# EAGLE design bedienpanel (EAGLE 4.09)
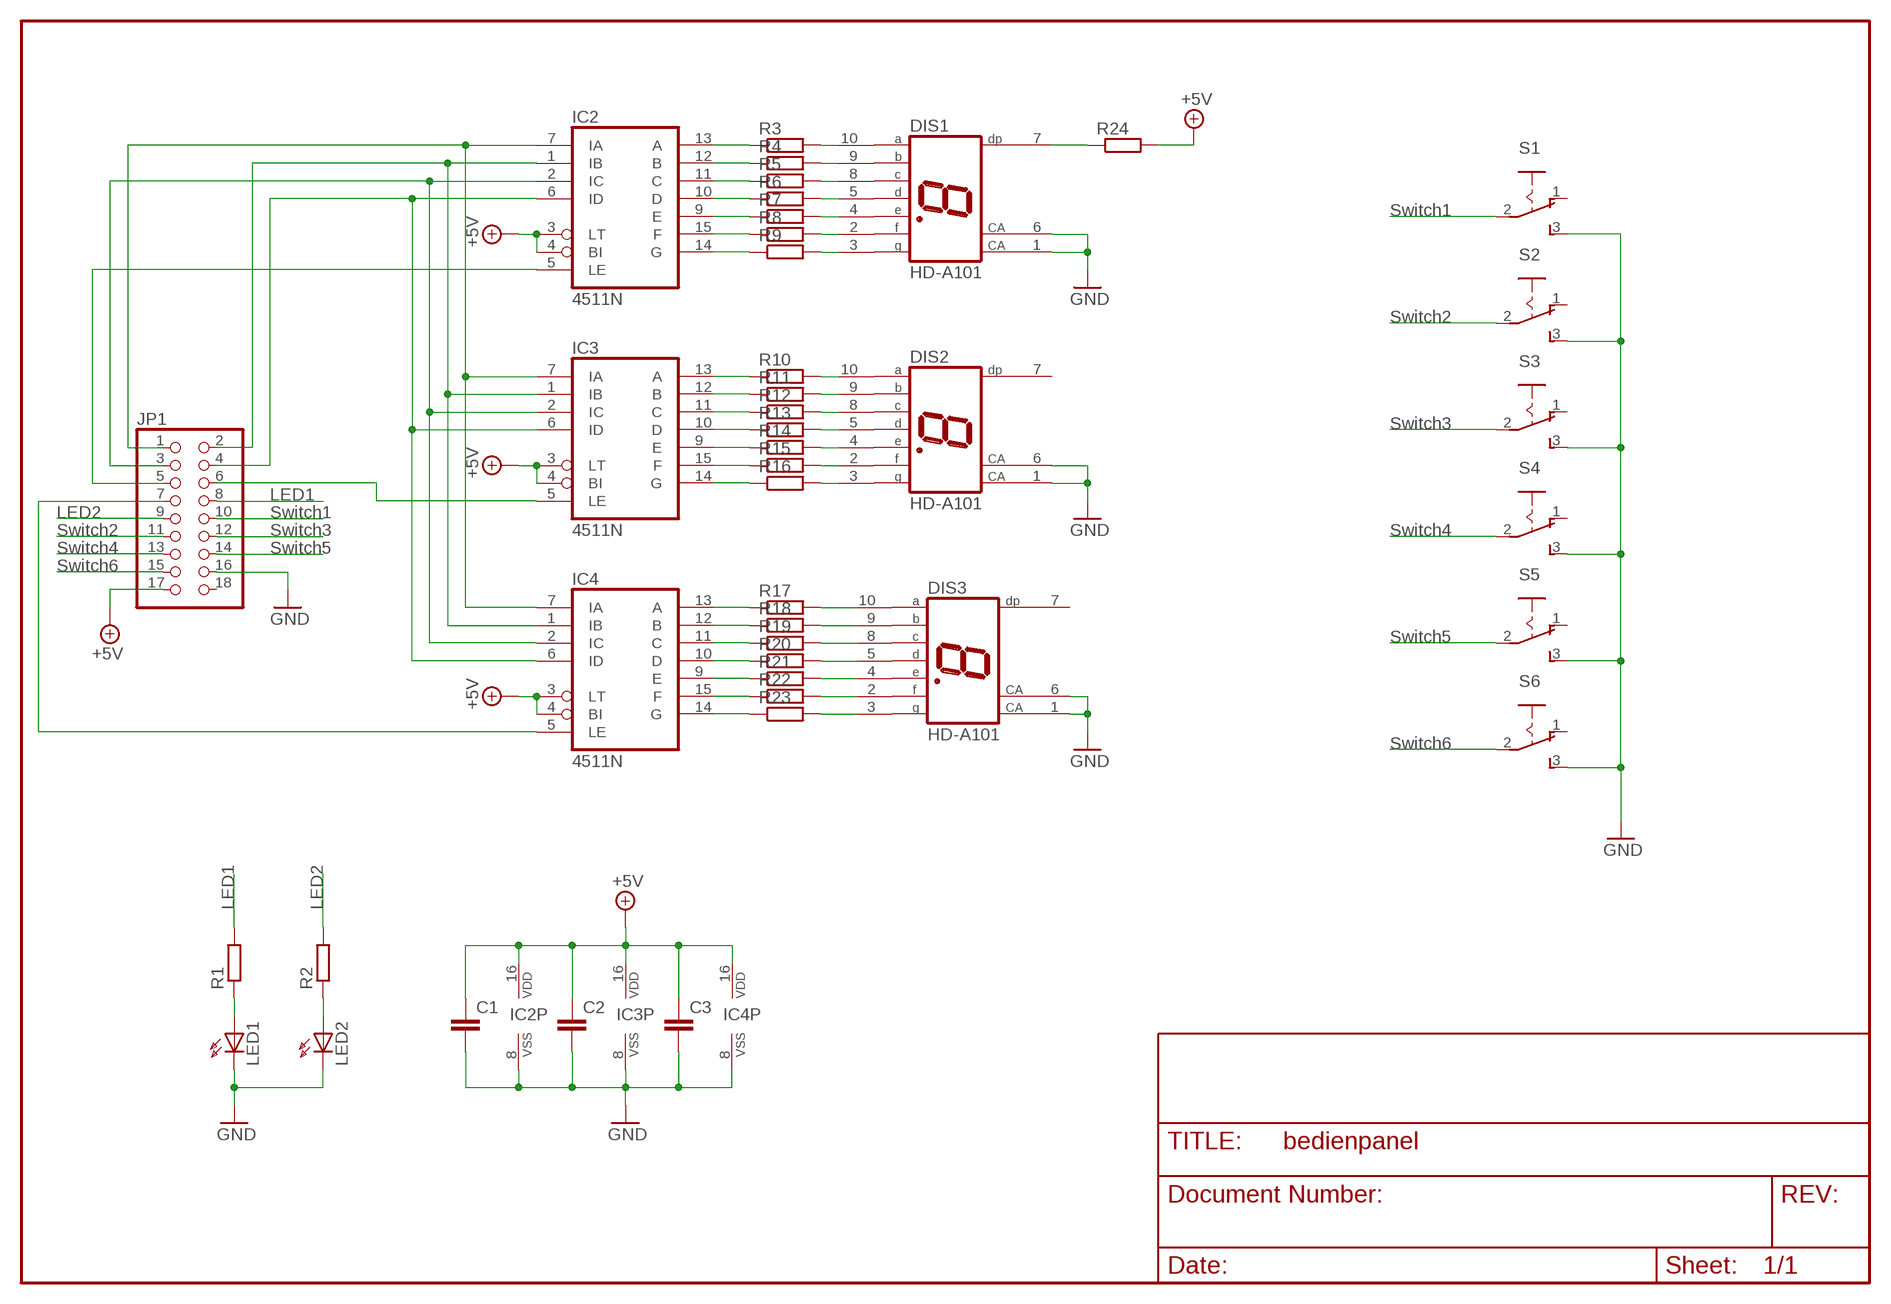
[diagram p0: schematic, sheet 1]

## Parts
C1  C-EUC1206  [C1206]
C2  C-EUC1206  [C1206]
C3  C-EUC1206  [C1206]
DIS1  HD-A101  [HDSP-A]
DIS2  HD-A101  [HDSP-A]
DIS3  HD-A101  [HDSP-A]
IC2  4511N  [DIL16]
IC3  4511N  [DIL16]
IC4  4511N  [DIL16]
JP1  PINHD-2X9  [2X09]
LED1  LED3MM  [LED3MM]
LED2  LED3MM  [LED3MM]
R1  R-EU_R1206  [R1206]
R2  R-EU_R1206  [R1206]
R3  R-EU_M0805  [M0805]
R4  R-EU_M0805  [M0805]
R5  R-EU_M0805  [M0805]
R6  R-EU_M0805  [M0805]
R7  R-EU_M0805  [M0805]
R8  R-EU_M0805  [M0805]
R9  R-EU_M0805  [M0805]
R10  R-EU_M0805  [M0805]
R11  R-EU_M0805  [M0805]
R12  R-EU_M0805  [M0805]
R13  R-EU_M0805  [M0805]
R14  R-EU_M0805  [M0805]
R15  R-EU_M0805  [M0805]
R16  R-EU_M0805  [M0805]
R17  R-EU_M0805  [M0805]
R18  R-EU_M0805  [M0805]
R19  R-EU_M0805  [M0805]
R20  R-EU_M0805  [M0805]
R21  R-EU_M0805  [M0805]
R22  R-EU_M0805  [M0805]
R23  R-EU_M0805  [M0805]
R24  R-EU_M0805  [M0805]
S1  255SB  [255SB]
S2  255SB  [255SB]
S3  255SB  [255SB]
S4  255SB  [255SB]
S5  255SB  [255SB]
S6  255SB  [255SB]

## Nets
+5V: C1.1 C2.1 C3.1 IC2.3(LT) IC2.4(BI) IC2.16(VDD) IC3.3(LT) IC3.4(BI) IC3.16(VDD) IC4.3(LT) IC4.4(BI) IC4.16(VDD) JP1.17 R24.2
GND: C1.2 C2.2 C3.2 DIS1.1(CA) DIS1.6(CA) DIS2.1(CA) DIS2.6(CA) DIS3.1(CA) DIS3.6(CA) IC2.8(VSS) IC3.8(VSS) IC4.8(VSS) JP1.16 LED1.K(C) LED2.K(C) S1.3(S) S2.3(S) S3.3(S) S4.3(S) S5.3(S) S6.3(S)
LED1: JP1.8 R1.2
LED2: JP1.9 R2.2
N$1: IC2.6(ID) IC3.6(ID) IC4.6(ID) JP1.4
N$2: IC2.7(IA) IC3.7(IA) IC4.7(IA) JP1.1
N$3: IC2.5(LE) JP1.5
N$4: IC2.2(IC) IC3.2(IC) IC4.2(IC) JP1.3
N$5: IC2.1(IB) IC3.1(IB) IC4.1(IB) JP1.2
N$6: IC3.5(LE) JP1.6
N$7: IC4.5(LE) JP1.7
N$8: IC2.13(A) R3.1
N$9: IC2.12(B) R4.1
N$10: IC2.11(C) R5.1
N$11: IC2.10(D) R6.1
N$12: IC2.9(E) R7.1
N$13: IC2.15(F) R8.1
N$14: IC2.14(G) R9.1
N$15: IC3.13(A) R10.1
N$16: IC3.12(B) R11.1
N$17: IC3.11(C) R12.1
N$18: IC3.10(D) R13.1
N$19: IC3.9(E) R14.1
N$20: IC3.15(F) R15.1
N$21: IC3.14(G) R16.1
N$22: IC4.13(A) R17.1
N$23: IC4.12(B) R18.1
N$24: IC4.11(C) R19.1
N$25: IC4.10(D) R20.1
N$26: IC4.9(E) R21.1
N$27: IC4.15(F) R22.1
N$28: IC4.14(G) R23.1
N$29: LED1.A R1.1
N$30: LED2.A R2.1
N$31: DIS1.10(A) R3.2
N$32: DIS1.9(B) R4.2
N$33: DIS1.8(C) R5.2
N$34: DIS1.5(D) R6.2
N$35: DIS1.4(E) R7.2
N$36: DIS1.2(F) R8.2
N$37: DIS1.3(G) R9.2
N$38: DIS2.10(A) R10.2
N$39: DIS2.9(B) R11.2
N$40: DIS2.8(C) R12.2
N$41: DIS2.5(D) R13.2
N$42: DIS2.4(E) R14.2
N$43: DIS2.2(F) R15.2
N$44: DIS2.3(G) R16.2
N$45: DIS3.10(A) R17.2
N$46: DIS3.9(B) R18.2
N$47: DIS3.8(C) R19.2
N$48: DIS3.5(D) R20.2
N$49: DIS3.4(E) R21.2
N$50: DIS3.2(F) R22.2
N$51: DIS3.3(G) R23.2
N$52: DIS1.7(DP) R24.1
SWITCH1: JP1.10 S1.2(P)
SWITCH2: JP1.11 S2.2(P)
SWITCH3: JP1.12 S3.2(P)
SWITCH4: JP1.13 S4.2(P)
SWITCH5: JP1.14 S5.2(P)
SWITCH6: JP1.15 S6.2(P)
Unconnected: DIS2.7(DP) DIS3.7(DP) JP1.18 S1.1(O) S2.1(O) S3.1(O) S4.1(O) S5.1(O) S6.1(O)

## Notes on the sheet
- Switch1
- Switch2
- Switch3
- LED1
- LED2 | Switch1
- Switch2 | Switch3 | Switch4
- Switch4 | Switch5
- Switch6
- Switch5
- Switch6
- LED1 | LED2

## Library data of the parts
C1-C3 = rcl:C-EU: CAPACITOR, European symbol
DIS1-DIS3 = display-hp:HD-A101: LED DISPLAY 1-character 7 segment, decimal point right
IC2-IC4 = 45xx:4511: BCD to 7-segment LATCH/DECODER/DRIVER
JP1 = pinhead:PINHD-2X9: PIN HEADER
LED1 LED2 = led:LED: LED
R1-R24 = rcl:R-EU_: RESISTOR, European symbol
S1-S6 = switch:255SB: SLIDING SWITCH distributor Buerklin, 11G810

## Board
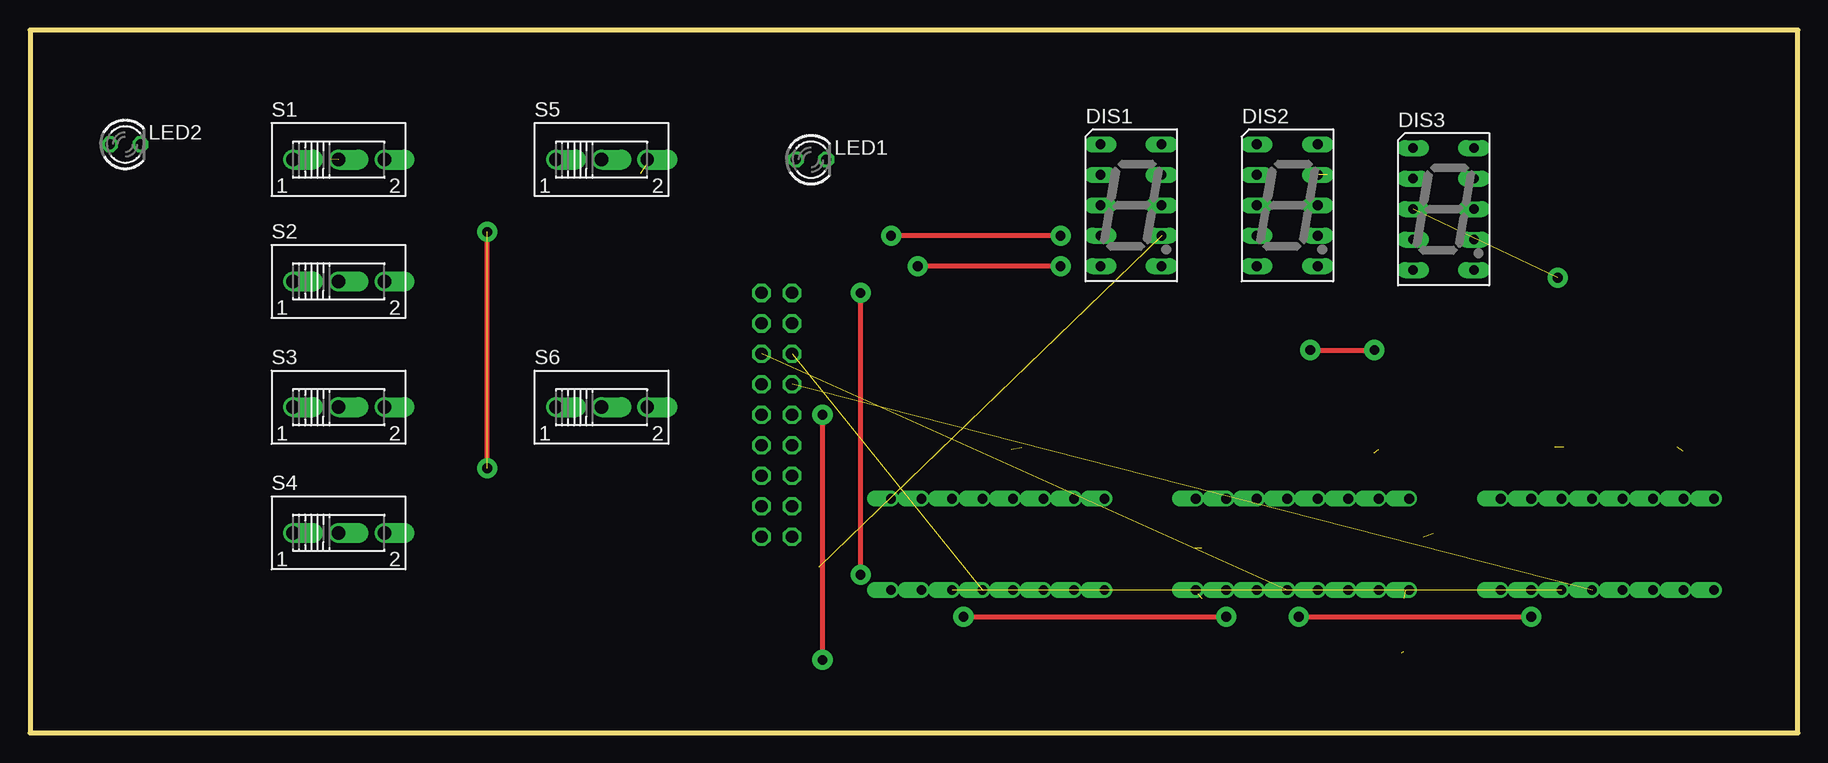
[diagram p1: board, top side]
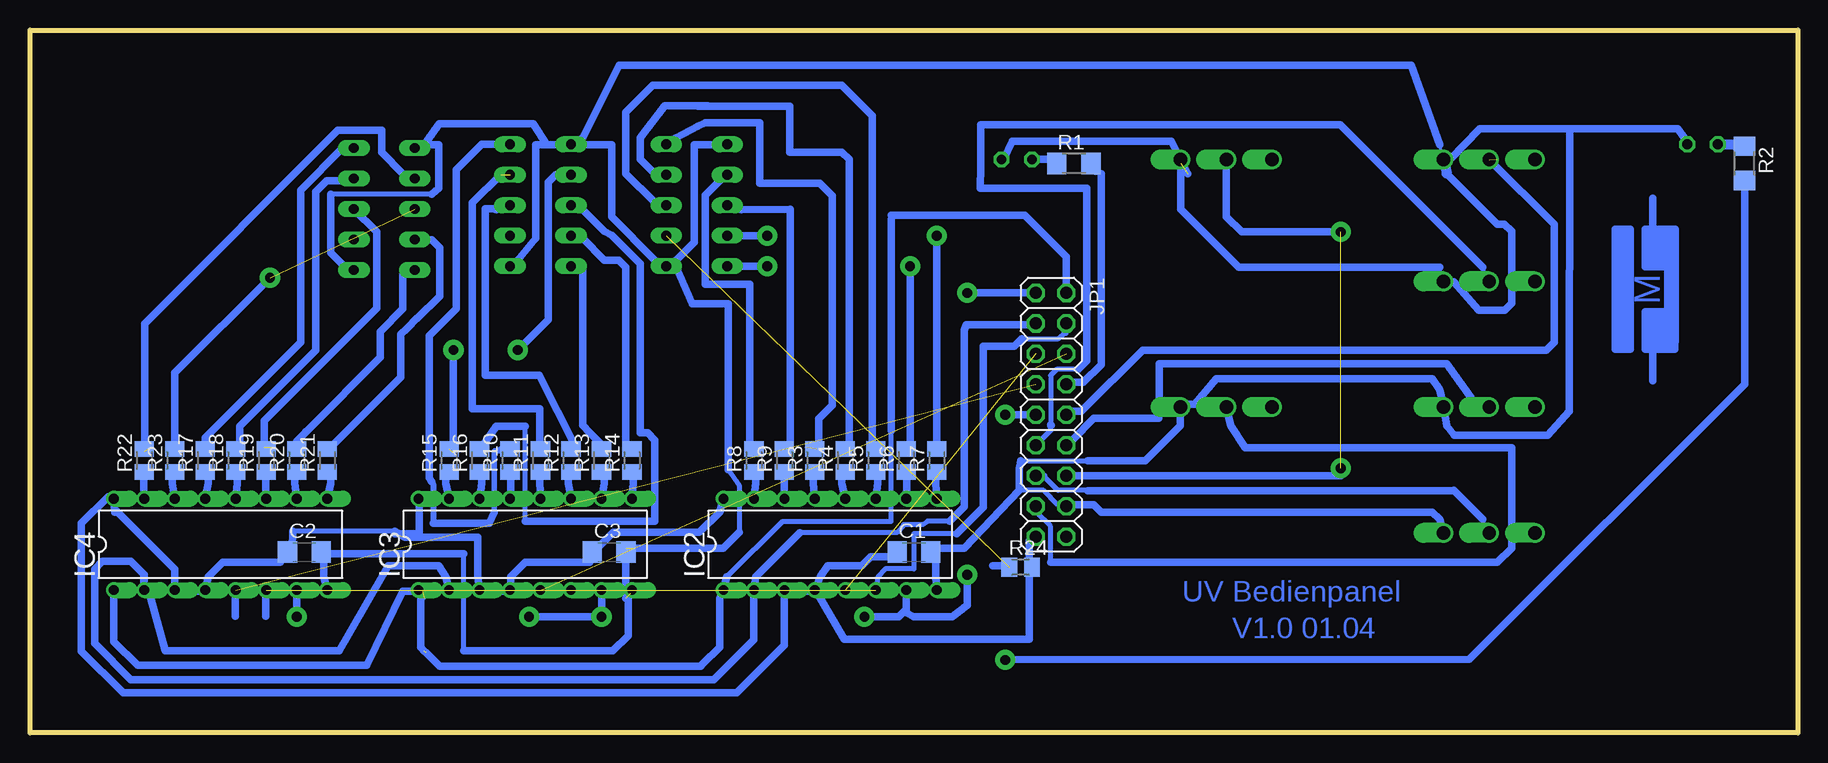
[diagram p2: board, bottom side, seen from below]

Size 147.32 x 58.58 mm. Coordinates in mm from the lower left corner, seen from the top.
Outline: 0,0 147.32,0 147.32,58.58 0,58.58 0,0
Copper layers used: Top, Bottom

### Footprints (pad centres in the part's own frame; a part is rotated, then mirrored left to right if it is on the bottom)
C1206 = smd 1.6 x 1.8: 1 -1.4,0; 2 1.4,0
HDSP-A = drill 0.813 long: 1 -2.54,5.08; 2 -2.54,2.54; 3 -2.54,0; 4 -2.54,-2.54; 5 -2.54,-5.08; 6 2.54,-5.08; 7 2.54,-2.54; 8 2.54,0; 9 2.54,2.54; 10 2.54,5.08
DIL16 = drill 0.813 offset: 1 -8.89,-3.81; 2 -6.35,-3.81; 3 -3.81,-3.81; 4 -1.27,-3.81; 5 1.27,-3.81; 6 3.81,-3.81; 7 6.35,-3.81; 8 8.89,-3.81; 9 8.89,3.81; 10 6.35,3.81; 11 3.81,3.81; 12 1.27,3.81; 13 -1.27,3.81; 14 -3.81,3.81; 15 -6.35,3.81; 16 -8.89,3.81
2X09 = drill 1.016 octagon: 1 -10.16,-1.27; 2 -10.16,1.27; 3 -7.62,-1.27; 4 -7.62,1.27; 5 -5.08,-1.27; 6 -5.08,1.27; 7 -2.54,-1.27; 8 -2.54,1.27; 9 0,-1.27; 10 0,1.27; 11 2.54,-1.27; 12 2.54,1.27; 13 5.08,-1.27; 14 5.08,1.27; 15 7.62,-1.27; 16 7.62,1.27; 17 10.16,-1.27; 18 10.16,1.27
LED3MM = drill 0.813 octagon: A -1.27,0; K 1.27,0
R1206 = smd 1.6 x 1.803: 1 -1.422,0; 2 1.422,0
M0805 = smd 1.3 x 1.6: 1 -0.95,0; 2 0.95,0
255SB = drill 1.118 offset: 1 -3.81,0; 2 0,0; 3 3.81,0

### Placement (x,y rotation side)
C1  73.66,15.08 0 bottom
C2  124.46,15.08 0 bottom
C3  99.06,15.08 0 bottom
DIS1  91.76,43.97 0 top
DIS2  104.77,43.97 0 top
DIS3  117.79,43.66 0 top
IC2  80.64,15.72 0 bottom
IC3  106.05,15.72 0 bottom
IC4  131.45,15.72 0 bottom
JP1  62.23,26.51 270 bottom
LED1  65.09,47.78 0 top
LED2  7.94,49.05 0 top
R1  60.33,47.47 0 bottom
R2  4.44,47.47 270 bottom
R3  81.91,22.7 90 bottom
R4  79.38,22.7 90 bottom
R5  76.83,22.7 90 bottom
R6  74.3,22.7 90 bottom
R7  71.75,22.7 90 bottom
R8  86.99,22.7 90 bottom
R9  84.45,22.7 90 bottom
R10  107.31,22.7 90 bottom
R11  104.77,22.7 90 bottom
R12  102.23,22.7 90 bottom
R13  99.69,22.7 90 bottom
R14  97.16,22.7 90 bottom
R15  112.39,22.7 90 bottom
R16  109.85,22.7 90 bottom
R17  132.72,22.7 90 bottom
R18  130.18,22.7 90 bottom
R19  127.63,22.7 90 bottom
R20  125.09,22.7 90 bottom
R21  122.55,22.7 90 bottom
R22  137.8,22.7 90 bottom
R23  135.26,22.7 90 bottom
R24  64.77,13.81 0 bottom
S1  25.72,47.78 0 top
S2  25.72,37.62 0 top
S3  25.72,27.15 0 top
S4  25.72,16.67 0 top
S5  47.62,47.78 0 top
S6  47.62,27.15 0 top
U$1  [LOGO]  12.73,36.96 270 top

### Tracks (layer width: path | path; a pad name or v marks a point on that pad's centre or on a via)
+5V  (1 unrouted)
  Bottom 0.254: 109.66,11.81 IC3.3 | 100.06,15.41 C3.1 100.66,14.21 | 64.06,14.21 R24.2 64.06,13.61 | IC2.4 82.06,11.81 | 75.46,14.68 C1.1 | IC4.4 133.06,11.81 | 134.86,11.81 IC4.3 | 125.48,15.41 C2.1 126.46,14.21
  Bottom 0.406: 116.92,16.83 125.43,16.83
  Bottom 0.61: 109.66,11.81 107.86,11.81 IC3.4 107.26,13.01 106.06,14.21 100.66,14.21 | 100.06,15.41 98.74,16.73 91.54,16.73 89.86,18.41 IC2.16 | 64.06,14.21 64.06,16.01 JP1.17 | 82.06,11.81 83.86,11.81 IC2.3 84.46,7.43 84.46,7.3 88.42,3.33 139.54,3.33 143.03,6.83 143.03,17.46 140.86,19.64 | 75.46,14.68 77.26,14.68 78.02,13.92 80.86,13.92 81.46,13.01 IC2.4 81.46,11.21 79.47,7.82 64.06,7.82 64.06,13.61 | 133.06,11.81 134.86,11.81 | 116.92,16.83 116.1,16.32 110.01,16.32 110.01,13.01 IC3.3 | 125.43,16.83 125.48,15.41 | IC3.16 114.9,18.41 114.9,16.6 116.94,16.6 | 126.46,14.21 131.26,14.21 132.46,13.01 IC4.4 | IC4.3 135.25,13.65 140.18,18.57 140.26,18.49 140.26,18.41 IC4.16 140.86,19.61 140.86,19.64 | 140.81,19.69 140.86,19.64
GND  (3 unrouted)
  Bottom 0.254: 122.86,14.94 C2.2 | DIS2.1 101.26,49.01 | 97.06,15.41 C3.2 | DIS1.6 93.46,38.81 | 71.86,14.21 C1.2 71.86,15.41 | 61.66,19.01 JP1.16 60.46,19.01 | 28.95,47.81 29.26,47.81 | 29.86,38.81 S2.3 29.26,37.61 28.66,37.61 | S1.3 29.86,49.01
  Bottom 0.406: 111.18,6.83 111.18,14.94 | 113.86,44.89 122.26,44.89 | 89.14,21.92 88.22,20.65 88.22,16.72 | 61.66,19.01 62.86,20.21 64.87,20.21 | 64.75,22.7 54.38,22.7
  Bottom 0.61: C3.2 97.66,12.41 IC3.8 97.66,11.21 | IC4.8 122.86,13.01 122.86,14.94 111.18,14.94 | DIS1.1 90.46,49.01 91.98,49.01 91.98,40.89 93.46,39.41 DIS1.6 95.26,39.41 98.86,43.01 98.86,49.01 101.26,49.01 | 104.26,49.01 103.06,49.01 DIS2.1 101.26,49.61 98.22,55.66 32.22,55.66 29.86,49.01 | 104.26,49.01 105.18,49.01 105.18,41.21 106.66,39.41 DIS2.6 | 114.46,49.01 113.2,50.75 105.4,50.75 104.26,49.01 | 122.26,44.89 122.26,40.01 121.06,38.81 DIS3.6 | 113.86,44.89 113.26,45.41 113.26,49.01 114.46,49.01 | 114.46,49.01 DIS3.1 | 89.14,21.92 89.14,35.77 92.14,35.77 93.46,38.81 | 71.86,14.21 71.86,13.01 IC2.8 | 71.86,15.41 69.46,15.41 64.87,20.21 64.87,22.01 64.75,22.7 | 60.46,19.01 58.66,19.01 58.06,18.41 30.46,18.41 29.86,17.81 S4.3 | 54.38,22.7 51.46,25.61 S6.3 50.86,27.41 50.26,27.41 48.46,29.52 30.46,29.52 29.86,28.61 S3.3 29.26,25.61 28.63,24.8 20.83,24.8 19.06,26.81 19.03,50.37 | 19.03,50.37 26.51,50.37 28.95,47.81 | 19.03,50.37 10.03,50.37 9.46,49.61 LED2.K | LED1.K 66.18,47.81 65.45,49.32 52.22,49.32 S5.3 50.86,46.61 | 29.26,46.61 25.06,42.41 24.46,42.41 23.86,41.81 23.86,35.81 23.82,35.81 24.42,35.21 26.58,35.21 28.66,37.61 | 29.86,38.81 46.58,38.81 51.43,43.66 51.43,47.47 | 88.22,16.72 89.53,15.4 97.63,15.4 | 111.18,6.83 98.74,6.83 97.47,8.1 97.47,11.43 97.31,11.59
  Bottom 0.813: 29.26,47.81 S1.3 29.26,46.61
LED1
  Bottom 0.254: 58.06,46.61 58.66,46.61 R1.2
  Bottom 0.61: JP1.8 60.46,29.21 59.53,29.21 58.06,30.68 58.06,46.61
LED2  (via drill 0.81 pad 1.68)
  Top 0.406: v66.04,26.51 v66.04,6.09
  Bottom 0.406: v66.04,26.51 JP1.9
  Bottom 0.61: JP1.9 v66.04,26.51 | v66.04,6.09 27.37,6.12 4.44,29.05 R2.2
N$1  (2 unrouted)
  Bottom 0.406: 70.09,16.61 73.66,16.61 73.66,13.67 76.06,13.67 76.66,13.01 IC2.6 | 64.66,32.87 61.63,32.87 61.06,33.41
  Bottom 0.61: 70.09,16.61 67.88,18.8 67.88,32.21 65.29,32.21 64.66,32.87 | 61.06,33.41 JP1.4
N$2  (via drill 0.81 pad 1.68)
  Top 0.406: v69.21,13.18 v69.21,36.67 | v77.79,9.68 v99.69,9.68 | v105.73,9.68 v125.09,9.68
  Bottom 0.406: IC2.7 74.29,10 | v99.69,9.68 IC3.7 | 125.09,11.59 125.41,11.91
  Bottom 0.61: 74.29,10 73.66,9.68 70.48,9.68 69.21,10.64 v69.21,13.18 | v69.21,36.67 JP1.1 | IC2.7 74.29,10.32 74.93,9.68 v77.79,9.68 | IC3.7 v99.69,9.68 v105.73,9.68 | 125.41,11.91 IC4.7 | v125.09,9.68 125.09,11.59
N$3  (1 unrouted)
N$4
  Bottom 0.254: 64.06,34.01 JP1.3
  Bottom 0.406: 70.66,17.65 72.52,17.65 72.93,17.36 74.52,17.36 75.06,16.7 83.15,16.7 | 86.85,13.01 86.86,13.01
  Bottom 0.61: IC3.2 112.66,13.01 113.26,13.92 117.46,13.92 121.54,6.83 136.06,6.83 137.26,11.21 IC4.2 137.86,13.01 137.79,12.94 | 70.66,17.65 69.46,18.85 69.46,33.55 69.3,34 65.26,34.01 64.06,34.01 | 86.86,13.01 IC2.2 | 83.15,16.7 86.85,13.01 | 86.99,12.07 IC2.2 | IC2.2 86.99,7.78 90.33,4.45 138.91,4.45 141.92,7.46 141.92,13.65 141.29,14.29 138.91,14.29 137.79,13.18 137.79,12.94 | 137.79,12.7 137.79,12.94
N$5  (2 unrouted)
  Bottom 0.254: 114.46,11.21 IC3.1 115.06,11.81
  Bottom 0.406: 75.55,43.16 75.55,17.62 84.62,17.62 89.26,13.01
  Bottom 0.61: 115.06,11.81 116.26,11.81 119.26,5.63 138.35,5.63 140.33,7.62 IC4.1 | 75.55,43.16 64.41,43.14 60.96,39.69 JP1.2 | 89.26,13.01 IC2.1 89.86,11.21 89.86,7.14 91.28,5.72 | 91.28,5.72 | 91.28,5.72 91.44,5.56 113.19,5.56 114.3,6.67 | 114.3,6.67 | 114.46,6.83 | 114.78,11.75 114.62,11.91 | 114.78,11.91 114.78,11.75 | 114.46,6.83 114.78,7.14 114.78,11.75
N$6  (1 unrouted)
N$7  (1 unrouted)
N$8
  Bottom 0.254: R3.1 82.06,21.41
  Bottom 0.61: 82.06,21.41 82.06,20.81 IC2.13
N$9
  Bottom 0.254: R4.1 79.66,21.41
  Bottom 0.61: 79.66,21.41 79.66,20.81 IC2.12
N$10
  Bottom 0.254: R5.1 76.66,21.41
  Bottom 0.61: 76.66,21.41 76.66,20.81 IC2.11
N$11
  Bottom 0.254: R6.1 74.26,21.41
  Bottom 0.61: 74.26,21.41 74.26,20.81 IC2.10
N$12
  Bottom 0.254: R7.1 71.86,21.41
  Bottom 0.61: 71.86,21.41 71.86,20.81 IC2.9
N$13
  Bottom 0.254: R8.1 86.86,21.41
  Bottom 0.61: 86.86,21.41 86.86,20.81 IC2.15
N$14
  Bottom 0.254: R9.1 84.46,21.41
  Bottom 0.61: 84.46,21.41 84.46,20.81 IC2.14
N$15
  Bottom 0.254: R10.1 107.26,21.41
  Bottom 0.61: 107.26,21.41 107.26,20.81 IC3.13
N$16
  Bottom 0.254: R11.1 104.86,21.41
  Bottom 0.61: 104.86,21.41 104.86,20.81 IC3.12
N$17
  Bottom 0.254: R12.1 102.46,21.41
  Bottom 0.61: 102.46,21.41 102.46,20.81 IC3.11
N$18
  Bottom 0.254: R13.1 99.46,21.41
  Bottom 0.61: 99.46,21.41 99.46,20.81 IC3.10
N$19
  Bottom 0.254: R14.1 97.06,21.41
  Bottom 0.61: 97.06,21.41 97.06,20.81 IC3.9
N$20
  Bottom 0.254: R15.1 112.66,21.41
  Bottom 0.61: 112.66,21.41 112.66,20.81 IC3.15
N$21
  Bottom 0.254: R16.1 109.66,21.41
  Bottom 0.61: 109.66,21.41 109.66,20.81 IC3.14
N$22
  Bottom 0.254: R17.1 132.46,21.41
  Bottom 0.61: 132.46,21.41 132.46,20.81 IC4.13
N$23
  Bottom 0.254: R18.1 130.06,21.41
  Bottom 0.61: 130.06,21.41 130.06,20.81 IC4.12
N$24
  Bottom 0.254: R19.1 127.66,21.41
  Bottom 0.61: 127.66,21.41 127.66,20.81 IC4.11
N$25
  Bottom 0.254: R20.1 125.26,21.41
  Bottom 0.61: 125.26,21.41 125.26,20.81 IC4.10
N$26
  Bottom 0.254: R21.1 122.26,21.41
  Bottom 0.61: 122.26,21.41 122.26,20.81 IC4.9
N$27
  Bottom 0.254: R22.1 137.86,21.41
  Bottom 0.61: 137.86,21.41 137.86,20.81 IC4.15
N$28
  Bottom 0.254: R23.1 135.46,21.41
  Bottom 0.61: 135.46,21.41 135.46,20.81 IC4.14
N$29
  Bottom 0.254: 63.46,47.81 LED1.A | R1.1 62.26,47.81
  Bottom 0.61: 62.26,47.81 63.46,47.81
N$30
  Bottom 0.254: 6.46,49.01 LED2.A | R2.1 5.26,49.01
  Bottom 0.813: 5.26,49.01 6.46,49.01
N$31  (1 unrouted)
  Bottom 0.254: R3.2 82.66,23.81
  Bottom 0.61: DIS1.10 93.46,49.61 91.66,50.56 91.06,50.84 86.51,50.84 86.51,45.79 81.51,45.79 80.49,44.77 80.49,27.31 81.6,26.19 81.6,23.81 81.76,23.65
N$32
  Bottom 0.254: R4.2 79.06,23.81
  Bottom 0.61: 79.06,23.81 79.06,47.81 79.66,48.41 84,48.41 84,52.24 91.66,52.24 90.83,52.27 94.43,52.27 96.46,49.61 96.46,47.81 95.26,46.61 DIS1.9
N$33
  Bottom 0.254: R5.2 77.26,23.81
  Bottom 0.61: DIS1.8 95.26,44.21 97.66,46.61 97.66,51.72 95.41,53.98 79.69,53.98 77.15,51.44 77.15,23.91 77.26,23.81
N$34  (via drill 0.81 pad 1.68)
  Top 0.406: v85.88,38.89 v73.98,38.89
  Bottom 0.406: 73.98,23.65 R6.2
  Bottom 0.61: DIS1.5 v85.88,38.89 | v73.98,38.89 73.98,23.65
N$35  (via drill 0.81 pad 1.68)
  Top 0.406: v85.88,41.43 v71.75,41.43
  Bottom 0.406: 71.75,23.34 R7.2
  Bottom 0.61: DIS1.4 v85.88,41.43 | v71.75,41.43 R7.2
N$36
  Bottom 0.254: R8.2 87.46,23.81
  Bottom 0.61: 87.46,23.81 87.36,23.81 87.36,37.38 91.06,37.38 91.06,44.81 89.86,46.01 DIS1.2
N$37
  Bottom 0.254: R9.2 83.95,24.28
  Bottom 0.61: 83.95,24.28 83.95,43.62 88.06,43.61 DIS1.3
N$38
  Bottom 0.254: 107.86,23.81 R10.2
  Bottom 0.406: 108.62,18.41 108.62,23.49 107.86,23.81 | 113.7,17.49 113.7,20.77 113.85,20.93 113.99,21.06 | 113.89,20.98 113.89,20.92 113.69,20.71 113.69,17.67 113.51,17.49 109.22,17.49 108.81,17.91 108.81,18.2 108.66,18.35 108.66,18.53 108.6,18.59 108.6,23.52 107.45,23.52 R10.2 | 107.25,23.73 R10.2 | R10.2
  Bottom 0.61: 113.7,17.49 109.06,17.49 108.62,18.41 | DIS2.10 109.66,49.05 111.79,46.92 111.79,35.34 114.04,33.09 114.04,21.29 113.89,20.98 | 113.85,20.93
N$39  (1 unrouted)
  Bottom 0.254: R11.2 104.82,23.81
  Bottom 0.61: 104.82,23.81 104.82,27.04 110.45,27.04 110.45,43.96 110.45,44.17 108.11,46.51
N$40
  Bottom 0.254: R12.2 101.86,23.81
  Bottom 0.61: 101.86,23.81 104.87,29.81 109.38,29.81 109.38,43.68 108.78,43.68 108.46,43.61 DIS2.8
N$41
  Bottom 0.254: 101.26,38.81 DIS2.5 | R13.2 99.46,23.81
  Bottom 0.61: 101.26,38.81 101.26,25.64 100.66,25.01 99.46,23.81
N$42
  Bottom 0.254: R14.2 97.66,23.81
  Bottom 0.61: 97.66,23.81 97.66,38.81 98.26,39.41 99.46,39.41 101.26,41.21 DIS2.4
N$43  (via drill 0.81 pad 1.68)  (1 unrouted)
  Top 0.406: v106.68,31.91 v112.03,31.91
  Bottom 0.61: DIS2.2 103.5,46.51 104.14,45.88 104.14,34.45 v106.68,31.91 | v112.03,31.91 112.03,23.34
N$44
  Bottom 0.254: 109.66,23.81 R16.2
  Bottom 0.406: 106.06,17.65 106.06,25.58
  Bottom 0.61: 106.06,17.65 95.26,17.65 95.26,24.41 95.86,25.01 96.46,25.01 96.46,39.09 98.86,41.49 99.46,41.81 101.26,43.61 DIS2.3 | 106.06,25.58 108.46,25.58 109.66,23.81
N$45
  Bottom 0.61: DIS3.10 121.28,48.74 124.78,45.24 124.78,32.54 132.71,24.61 R17.2
N$46
  Bottom 0.61: DIS3.9 121.06,46.01 122.59,46.01 123.51,45.09 123.51,31.91 129.86,25.56 129.86,23.5 130.01,23.65 R18.2
N$47  (1 unrouted)
  Bottom 0.254: R19.2 127.06,23.81
  Bottom 0.61: DIS3.8 118.43,41.75 118.43,35.4 127.79,26.04 127.79,23.81
N$48
  Bottom 0.254: 116.26,38.21 DIS3.5 | 124.66,23.81 R20.2
  Bottom 0.61: 124.66,23.81 124.67,23.81 125.09,23.81 125.09,24.32 124.09,25.32 124.11,25.32 | 116.26,38.21 116.26,35.33 118.15,33.45 118.15,31.29 124.11,25.32 | 124.35,25.09 124.11,25.32
N$49
  Bottom 0.254: 122.26,23.81 R21.2
  Bottom 0.61: DIS3.4 113.85,41.12 113.18,40.45 113.18,36.4 115.04,34.54 115.07,34.54 115.87,33.74 115.9,33.74 116.43,33.21 116.43,29.63 122.26,23.81 | 122.4,23.67 122.26,23.81 | 122.26,23.81
N$50  (1 unrouted)
  Bottom 0.254: 137.26,23.81 R22.2
  Bottom 0.61: 137.77,23.49 137.77,34.1 121.66,50.21 118.02,50.21 118.02,48.37 116.26,46.61 DIS3.2
N$51  (1 unrouted)
  Bottom 0.61: R23.2 135.25,30 127.32,37.94
N$52  (1 unrouted)
N$53  (1 unrouted)
N$54  (via drill 0.81 pad 1.68)
  other vias: 127.32,37.94
N$55
  Bottom 0.61: 28.85,20.2 59.19,20.2
N$56
  Bottom 0.61: 59.17,22.69 54.43,22.69
N$57
  Bottom 0.61: 75.53,42.82 75.53,25.2
N$58  (via drill 0.81)
  other vias: 60.94,16.33
N$59  (via drill 0.81)
  other vias: 63.51,16.33
N$60  (via drill 0.81)
  other vias: 63.51,18.87
N$61  (via drill 0.81)
  other vias: 60.97,18.9
N$62  (via drill 0.81)
  other vias: 60.97,21.41
N$63  (via drill 0.81)
  other vias: 63.51,21.41
N$64  (via drill 0.81)
  other vias: 63.48,23.98
N$65  (via drill 0.81)
  other vias: 60.97,23.98
N$66  (via drill 0.81)
  other vias: 63.45,26.55
N$67  (via drill 0.81)
  other vias: 60.97,26.52
N$68  (via drill 0.81)
  other vias: 60.97,29.03
N$69  (via drill 0.81)
  other vias: 63.48,29
N$70  (via drill 0.81)
  other vias: 63.51,31.57
N$71  (via drill 0.81)
  other vias: 60.97,31.57
N$72  (via drill 0.81)
  other vias: 60.97,34.11
N$73  (via drill 0.81)
  other vias: 60.97,36.66
N$74  (via drill 0.81)
  other vias: 63.48,36.62
N$75  (via drill 0.81)
  other vias: 63.48,34.11
N$76
  Bottom 0.61: 127.6,11.91 127.66,11.91 127.66,9.72
N$77
  Bottom 0.61: 130.2,11.91 130.24,11.91 130.24,9.72
N$78
  Bottom 0.61: 65.71,13.91 67.1,13.91
SWITCH1  (1 unrouted)
  Bottom 0.254: 60.46,26.81 JP1.10 | 25.06,47.81 S1.2
  Bottom 0.61: 60.46,26.81 59.71,26.81 54.61,31.91 20.95,31.91 20.32,32.54 20.32,42.39 S1.2
SWITCH2
  Bottom 0.254: S2.2 26.26,38.81
  Bottom 0.406: 62.26,25.61 62.26,29.81 61.77,30.29 59.97,30.29 | 62.25,25.75 62.25,25.67 62.25,25.22 JP1.11
  Bottom 0.61: 62.26,25.61 62.23,25.65 62.25,25.67 | 59.97,30.29 59.26,31.01 59.26,45.41 68.11,45.41 68.1,47.21 68.1,50.68 38.14,50.68 26.26,38.81
SWITCH3
  Bottom 0.61: 26.86,27.41 29.26,30.76 53.23,30.76 53.23,26.81 53.26,26.21 58.66,26.21 60.46,24.41 JP1.12 | S3.2 26.26,27.41
  Bottom 0.813: 26.26,27.41 26.86,27.41
SWITCH4
  Bottom 0.254: S4.2 26.26,17.81
  Bottom 0.406: 62.86,21.41 61.66,20.21 28.66,20.21
  Bottom 0.61: 26.26,17.81 28.66,20.21 | 62.86,21.41 JP1.13
SWITCH5  (via drill 0.81 pad 1.68)
  Top 0.406: v38.1,22.07 v38.1,41.75
  Bottom 0.406: 38.1,21.43 v38.1,22.07 | 47.62,48.1 S5.2
  Bottom 0.61: JP1.14 38.1,21.43 | v38.1,41.75 46.35,41.75 47.62,43.02 S5.2
SWITCH6
  Bottom 0.254: 63.46,18.41 JP1.15
  Bottom 0.406: 63.46,18.41 62.26,17.21 62.26,14.21
  Bottom 0.61: 62.26,14.21 25.06,14.21 23.86,15.41 23.86,23.77 46.06,23.77 47.26,25.61 S6.2

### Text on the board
Bottom: UV Bedienpanel | V1.0 01.04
